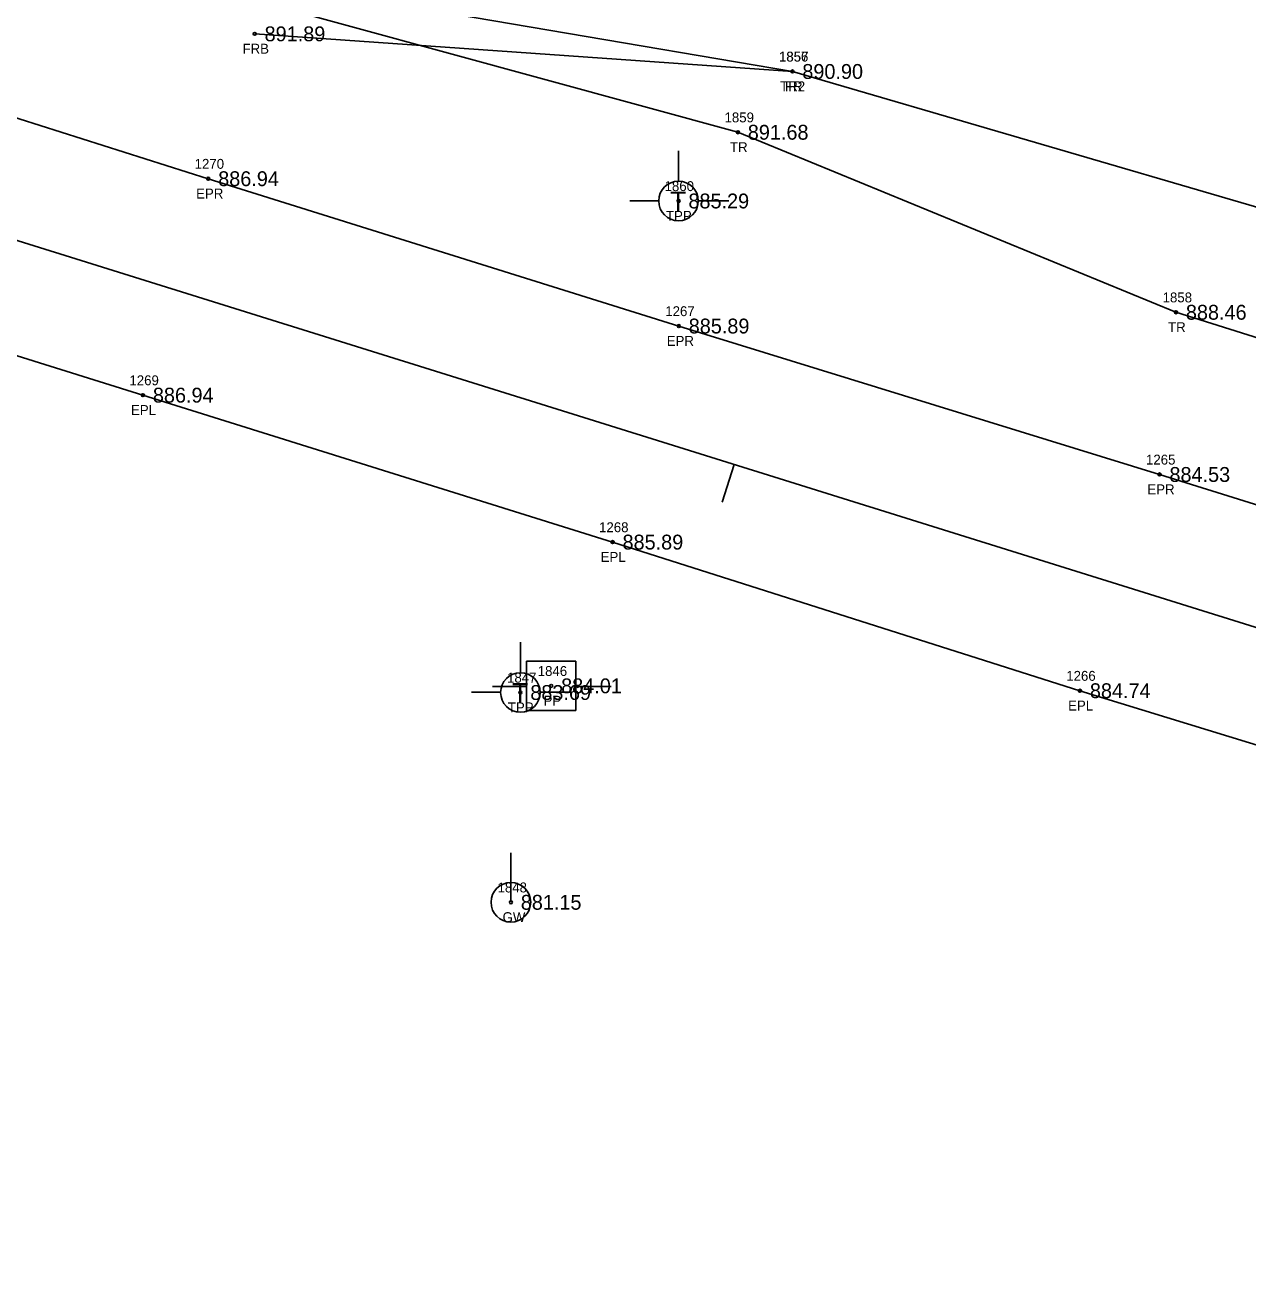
# Model space of a CAD drawing. Extents: x 1448136 to 1453623, y 1125056 to 1128842.
# Drawn here: x 1449747.7 to 1449871.2, y 1126660.1 to 1126787.2 of the extents above; entities that cross this region are included whole.
import ezdxf

# ---------------------------------------------------------------- set-up
doc = ezdxf.new("R2010")
doc.units = 0
for name, color, linetype in [('RD_EX_Fence_Other', 7, 'Continuous'), ('RD_EX_Fence_Other_txCode', 7, 'Continuous'), ('RD_EX_Road', 7, 'Continuous'), ('RD_EX_Road_txCode', 7, 'Continuous'), ('RD_EX_TX_Fence_Other_ELEV', 7, 'Continuous'), ('RD_EX_TX_Road_ELEV', 7, 'Continuous'), ('RD_EX_TX_UT_ELEV', 7, 'Continuous'), ('RD_EX_TX_VEG_ELEV', 7, 'Continuous'), ('RD_EX_UT', 7, 'Continuous'), ('RD_EX_UT_txCode', 7, 'Continuous'), ('RD_EX_VEG', 7, 'Continuous'), ('RD_EX_VEG_txCode', 7, 'Continuous'), ('RD_HC_Cl', 7, 'Continuous'), ('RD_HC_Data_Tic', 7, 'Continuous'), ('RD_HC_Survey_ELEV', 7, 'Continuous'), ('RD_SMD_Locator', 7, 'Continuous')]:
    doc.layers.add(name, color=color, linetype=linetype)

msp = doc.modelspace()

# ---------------------------------------------------------------- linework, layer by layer
at = {"layer": 'RD_EX_Fence_Other'}
msp.add_lwpolyline([(1450056.89, 1126784.04), (1450047.15, 1126748.04), (1450041.18, 1126724.82), (1450011.35, 1126731.86), (1449969.63, 1126743.17), (1449916.46, 1126756.27), (1449872.7, 1126768.68), (1449825.21, 1126782.55), (1449770.87, 1126786.35)], dxfattribs=at)
at = {"layer": 'RD_EX_Road'}
for points in [[(1450334.81, 1126677.22), (1450288.34, 1126667.77), (1450239.92, 1126662.52), (1450192.72, 1126661.45), (1450145.26, 1126665.09), (1450097.34, 1126672.81), (1450049.7, 1126684.25), (1450007.41, 1126696.7), (1449955.88, 1126712.65), (1449909.23, 1126727.21), (1449862.31, 1126741.85), (1449813.73, 1126756.84), (1449766.18, 1126771.72), (1449717.33, 1126787.19), (1449671.79, 1126801.4), (1449624.98, 1126815.8), (1449576.84, 1126830.74), (1449569.21, 1126834.03), (1449511.24, 1126851.67), (1449482.54, 1126860.68), (1449432.31, 1126877.02)], [(1450340.73, 1126655.01), (1450291.74, 1126645.33), (1450242.07, 1126639.91), (1450191.92, 1126637.95), (1450184.99, 1126636.16), (1450163.38, 1126634.92), (1450141.93, 1126638.08), (1450123.3, 1126641.98), (1450121.61, 1126644.88), (1450093.17, 1126650), (1450044.99, 1126661.93), (1449996.8, 1126675.54), (1449949.24, 1126690.23), (1449901.53, 1126705.51), (1449854.27, 1126720.01), (1449807.04, 1126735.02), (1449759.58, 1126749.86), (1449712.08, 1126764.7), (1449664.51, 1126779.32), (1449616.94, 1126794.11), (1449569.36, 1126808.87), (1449521.79, 1126823.57), (1449474.36, 1126838.35), (1449426.72, 1126853.6)]]:
    msp.add_lwpolyline(points, dxfattribs=at)
at = {"layer": 'RD_EX_UT'}
for p, q in [((1449813.7, 1126774.54), (1449813.7, 1126771.47)), ((1449808.77, 1126769.48), (1449811.7, 1126769.48)), ((1449815.7, 1126769.48), (1449818.77, 1126769.48)), ((1449797.72, 1126724.9), (1449797.72, 1126721.83)), ((1449803.33, 1126723.01), (1449798.33, 1126723.01)), ((1449798.33, 1126723.01), (1449798.33, 1126718.01)), ((1449803.33, 1126718.01), (1449803.33, 1126723.01)), ((1449792.79, 1126719.85), (1449795.72, 1126719.85)), ((1449794.9, 1126720.45), (1449798.37, 1126720.45)), ((1449799.72, 1126719.85), (1449802.79, 1126719.85)), ((1449803.26, 1126720.45), (1449806.9, 1126720.45)), ((1449798.33, 1126718.01), (1449803.33, 1126718.01)), ((1449796.76, 1126698.64), (1449796.76, 1126703.64))]:
    msp.add_line(p, q, dxfattribs=at)
for centre in [(1449813.7, 1126769.47), (1449797.72, 1126719.83), (1449796.76, 1126698.64)]:
    msp.add_circle(centre, 2, dxfattribs=at)
at = {"layer": 'RD_EX_VEG'}
for points in [[(1450497.14, 1126869.56), (1450516.22, 1126848.5), (1450549.56, 1126811.53), (1450532.56, 1126794.68), (1450460.23, 1126747.26), (1450374.14, 1126711.58), (1450359.93, 1126714.38), (1450327.4, 1126704.15), (1450192.75, 1126708.95), (1450138.86, 1126723.3), (1450098.59, 1126713.39), (1450034.93, 1126708.87), (1450011.45, 1126718.54), (1449911.15, 1126743.4), (1449863.97, 1126758.23), (1449819.7, 1126776.41), (1449751.34, 1126795.1)], [(1450056.89, 1126784.04), (1450047.15, 1126748.04), (1450041.18, 1126724.82), (1450011.35, 1126731.86), (1449969.63, 1126743.17), (1449916.46, 1126756.27), (1449872.7, 1126768.68), (1449825.21, 1126782.55), (1449751.34, 1126795.1)]]:
    msp.add_lwpolyline(points, dxfattribs=at)
at = {"layer": 'RD_HC_Cl'}
msp.add_line((1450033.34, 1126676.03), (1449295.29, 1126906.46), dxfattribs=at)
at = {"layer": 'RD_HC_Data_Tic'}
msp.add_line((1449819.31, 1126742.85), (1449818.11, 1126739.04), dxfattribs=at)
at = {"layer": 'RD_SMD_Locator'}
for centre in [(1449770.87, 1126786.35), (1449825.21, 1126782.55), (1449825.21, 1126782.55), (1449819.7, 1126776.41), (1449766.18, 1126771.72), (1449813.7, 1126769.47), (1449863.97, 1126758.23), (1449813.73, 1126756.84), (1449759.58, 1126749.86), (1449862.31, 1126741.85), (1449807.04, 1126735.02), (1449797.72, 1126719.83), (1449800.84, 1126720.5), (1449854.27, 1126720.01), (1449796.76, 1126698.64)]:
    msp.add_circle(centre, 0.15, dxfattribs=at)

# ---------------------------------------------------------------- texts
at = {"layer": 'RD_EX_Fence_Other_txCode'}
for s, p in [('FRB', (1449769.64, 1126784.35)), ('1857', (1449823.86, 1126783.55)), ('FR', (1449824.45, 1126780.55))]:
    msp.add_text(s, height=1, dxfattribs=at).set_placement(p)
at = {"layer": 'RD_EX_Road_txCode'}
for s, p in [('1270', (1449764.8, 1126772.72)), ('EPR', (1449764.95, 1126769.72)), ('1267', (1449812.36, 1126757.84)), ('EPR', (1449812.51, 1126754.84)), ('1269', (1449758.21, 1126750.86)), ('EPL', (1449758.37, 1126747.86)), ('1265', (1449860.94, 1126742.85)), ('EPR', (1449861.08, 1126739.85)), ('1268', (1449805.67, 1126736.02)), ('EPL', (1449805.83, 1126733.02)), ('1266', (1449852.88, 1126721.01)), ('EPL', (1449853.07, 1126718.01))]:
    msp.add_text(s, height=1, dxfattribs=at).set_placement(p)
at = {"layer": 'RD_EX_TX_Fence_Other_ELEV'}
for s, p in [('891.89', (1449771.87, 1126785.6)), ('890.90', (1449826.21, 1126781.8))]:
    msp.add_text(s, height=1.5, dxfattribs=at).set_placement(p)
at = {"layer": 'RD_EX_TX_Road_ELEV'}
for s, p in [('886.94', (1449767.18, 1126770.97)), ('885.89', (1449814.73, 1126756.09)), ('886.94', (1449760.58, 1126749.11)), ('884.53', (1449863.31, 1126741.1)), ('885.89', (1449808.04, 1126734.27)), ('884.74', (1449855.27, 1126719.26))]:
    msp.add_text(s, height=1.5, dxfattribs=at).set_placement(p)
at = {"layer": 'RD_EX_TX_UT_ELEV'}
for s, p in [('885.29', (1449814.7, 1126768.72)), ('883.69', (1449798.72, 1126719.08)), ('881.15', (1449797.76, 1126697.89))]:
    msp.add_text(s, height=1.5, dxfattribs=at).set_placement(p)
at = {"layer": 'RD_EX_TX_VEG_ELEV'}
for s, p in [('890.90', (1449826.21, 1126781.8)), ('891.68', (1449820.7, 1126775.66)), ('888.46', (1449864.97, 1126757.48))]:
    msp.add_text(s, height=1.5, dxfattribs=at).set_placement(p)
at = {"layer": 'RD_EX_UT'}
for p in [(1449812.85, 1126768.42), (1449796.87, 1126718.79)]:
    msp.add_text('T', height=2, dxfattribs=at).set_placement(p)
at = {"layer": 'RD_EX_UT_txCode'}
for s, p in [('1860', (1449812.29, 1126770.47)), ('TPP', (1449812.43, 1126767.47)), ('1846', (1449799.47, 1126721.5)), ('1847', (1449796.37, 1126720.83)), ('TPP', (1449796.45, 1126717.83)), ('PP', (1449800.06, 1126718.5)), ('1848', (1449795.41, 1126699.64)), ('GW', (1449795.92, 1126696.64))]:
    msp.add_text(s, height=1, dxfattribs=at).set_placement(p)
at = {"layer": 'RD_EX_VEG_txCode'}
for s, p in [('1856', (1449823.84, 1126783.55)), ('TR2', (1449823.97, 1126780.55)), ('1859', (1449818.35, 1126777.41)), ('TR', (1449818.9, 1126774.41)), ('1858', (1449862.62, 1126759.23)), ('TR', (1449863.17, 1126756.23))]:
    msp.add_text(s, height=1, dxfattribs=at).set_placement(p)
at = {"layer": 'RD_HC_Survey_ELEV'}
msp.add_text('884.01', height=1.5, dxfattribs=at).set_placement((1449801.84, 1126719.75))

doc.saveas('drawing.dxf')
